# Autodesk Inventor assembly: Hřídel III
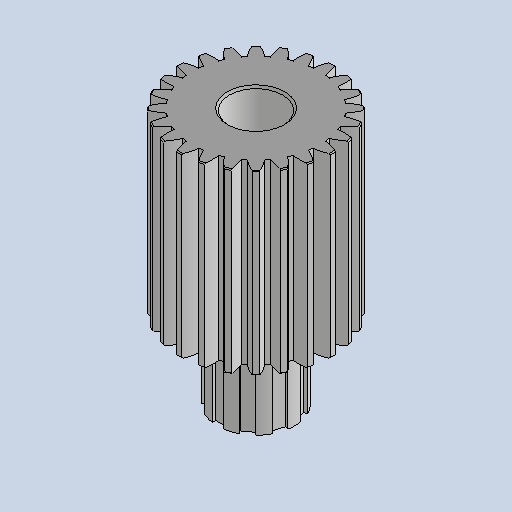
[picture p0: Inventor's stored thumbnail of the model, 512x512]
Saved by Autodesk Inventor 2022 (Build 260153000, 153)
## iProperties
Created: 2025-05
Part Number: Hřídel III
Document SubType Name: Assembly
Designer: jbart
Mass: 2650.81 g
Surface Area: 2605.11 cm^2
Volume: 2650.81 cm^3
Density: 1 g/cm^3
Author: jbart
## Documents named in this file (2)
- C:\Users\jbart\OneDrive\Dokumenty\Inventor\Převodovka navijáku\Hřídel III.iam
- C:\Users\jbart\OneDrive\Dokumenty\Inventor\Převodovka navijáku\Hřídel III\Design Accelerator\Čelní ozubená kola1.iam
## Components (1 placed, 1 different names)
1. Čelní ozubená kola:1 [sub-assembly]
